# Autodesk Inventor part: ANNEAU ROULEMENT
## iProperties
Created: 2004-11
Part Number: ANNEAU ROULEMENT
Document SubType Name: Modeling
Designer: Bruno
Manufacturer: Standard
Standards Organization: Custom
Author: Bruno
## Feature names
1. Base1
